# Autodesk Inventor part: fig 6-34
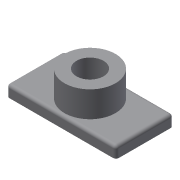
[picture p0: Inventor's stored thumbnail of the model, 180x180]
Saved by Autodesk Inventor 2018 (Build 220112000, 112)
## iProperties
Created: 2004-05
Part Number: fig 6-34
Document SubType Name: Modeling
Designer: CADCIM Technologies
Manufacturer: Standard
Standards Organization: Custom
Density: 1 g/cm^3
Material: Generic
Appearance: Default
Author: CADCIM Technologies
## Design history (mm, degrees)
sketch "Sketch1"
  geometry: L1 (-39.276, -18.692)-(33.721, -18.692); L2 (33.721, -18.692)-(33.721, 19.728); L3 (33.721, 19.728)-(-39.276, 19.728); L4 (-39.276, 19.728)-(-39.276, -18.692)
  constraints: 8 end point, 2 parallel, 1 horizontal, 1 perpendicular
extrude "Extrusion1" new body sketch "Sketch1" distance "d0" = 7.5; taper "d1" = 0 deg
sketch "Sketch2"
  geometry: C1 r 17 at (-2.778, 0.518)
  constraints: 1 centre point
  dimensions: "d16" = 34 diameter of C1
extrude "Extrusion2" join sketch "Sketch2" distance "d3" = 17.25; taper "d4" = 0 deg
hole "Hole1" diameter "d8" = 18; stored, may be unused: countersink angle "d12" = 90 deg, drill point angle "d14" = 118 deg; dims "d6" = 10, "d7" = 10, "d9" = 6, "d10" = 4, "d11" = 2, "d13" = 8
fillet "Fillet4" dims "d17" = 2
body "Solid1"
